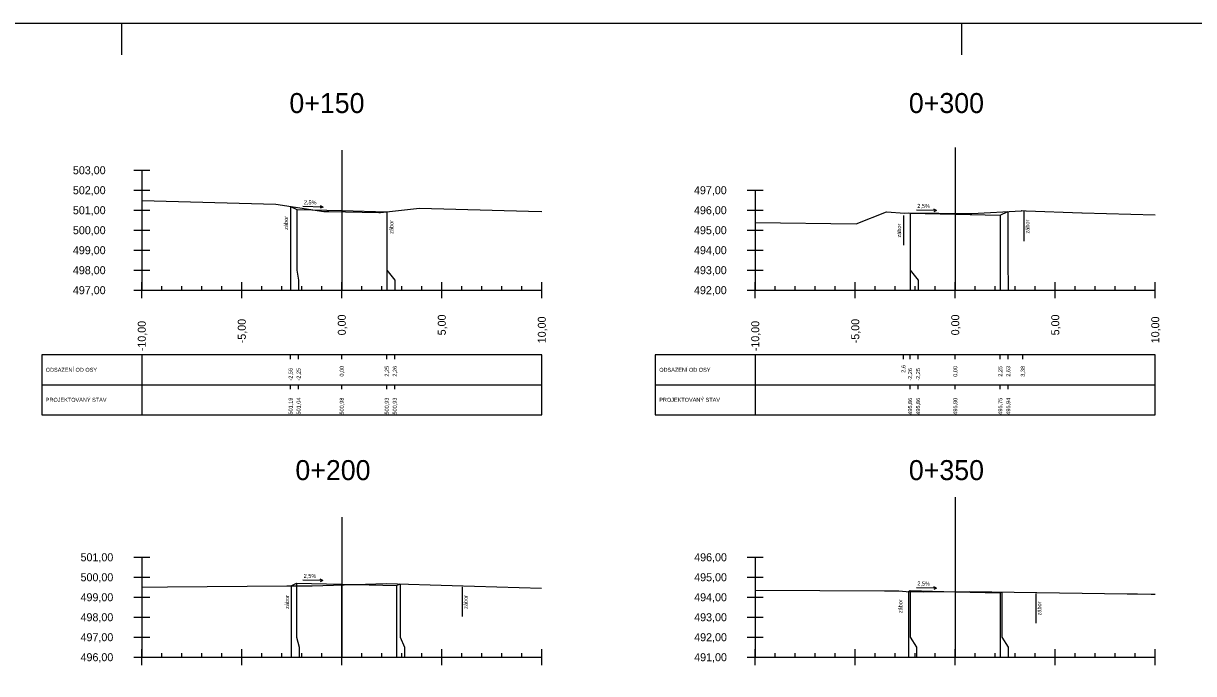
# Model space of a CAD drawing. Extents: x -631407 to -631215, y -1089700 to -1088598.
# Drawn here: x -631373.8 to -631315.3, y -1088714 to -1088681.5 of the extents above; entities that cross this region are included whole.
import ezdxf

# ---------------------------------------------------------------- set-up
doc = ezdxf.new("R2010")
doc.units = 0
for name, color, linetype in [('08_LEGENDA_HV', 7, 'Continuous'), ('59', 7, 'Continuous'), ('DTM-Breaklines', 7, 'Continuous'), ('NIVELETA_VYSKY', 7, 'Continuous'), ('REZ_BODY', 7, 'Continuous'), ('REZ_ODSTUPY', 7, 'Continuous'), ('REZ_POPIS', 7, 'Continuous'), ('REZ_RAMY', 7, 'Continuous'), ('REZ_STANICENI', 7, 'Continuous'), ('REZ_SVISLE', 7, 'Continuous'), ('REZ_TENKA', 7, 'Continuous'), ('REZ_TLUSTA', 7, 'Continuous'), ('TABULKA_POPIS', 7, 'Continuous'), ('TEREN', 7, 'Continuous'), ('zábor', 7, 'Continuous')]:
    doc.layers.add(name, color=color, linetype=linetype)

msp = doc.modelspace()

# ---------------------------------------------------------------- linework, layer by layer
at = {"layer": '08_LEGENDA_HV'}
msp.add_lwpolyline([(-631242.839, -1088740.87), (-631242.839, -1088681.47), (-631407.014, -1088681.47), (-631407.014, -1088740.87)], close=True, dxfattribs=at)
at = {"layer": '59'}
for p, q in [((-631368.243, -1088688.817), (-631367.443, -1088688.817)), ((-631367.843, -1088688.817), (-631367.843, -1088694.817)), ((-631368.243, -1088689.817), (-631367.443, -1088689.817)), ((-631337.571, -1088689.817), (-631336.771, -1088689.817)), ((-631337.171, -1088689.817), (-631337.171, -1088694.817)), ((-631368.243, -1088690.817), (-631367.443, -1088690.817)), ((-631337.571, -1088690.817), (-631336.771, -1088690.817)), ((-631368.243, -1088691.817), (-631367.443, -1088691.817)), ((-631337.571, -1088691.817), (-631336.771, -1088691.817)), ((-631368.243, -1088692.817), (-631367.443, -1088692.817)), ((-631337.571, -1088692.817), (-631336.771, -1088692.817)), ((-631368.243, -1088693.817), (-631367.443, -1088693.817)), ((-631337.571, -1088693.817), (-631336.771, -1088693.817)), ((-631368.243, -1088694.817), (-631367.443, -1088694.817)), ((-631337.571, -1088694.817), (-631336.771, -1088694.817)), ((-631368.243, -1088708.178), (-631367.443, -1088708.178)), ((-631367.843, -1088708.178), (-631367.843, -1088713.178)), ((-631337.571, -1088708.178), (-631336.771, -1088708.178)), ((-631337.171, -1088708.178), (-631337.171, -1088713.178)), ((-631368.243, -1088709.178), (-631367.443, -1088709.178)), ((-631337.571, -1088709.178), (-631336.771, -1088709.178)), ((-631368.243, -1088710.178), (-631367.443, -1088710.178)), ((-631337.571, -1088710.178), (-631336.771, -1088710.178)), ((-631368.243, -1088711.178), (-631367.443, -1088711.178)), ((-631337.571, -1088711.178), (-631336.771, -1088711.178)), ((-631368.243, -1088712.178), (-631367.443, -1088712.178)), ((-631337.571, -1088712.178), (-631336.771, -1088712.178)), ((-631368.243, -1088713.178), (-631367.443, -1088713.178)), ((-631337.571, -1088713.178), (-631336.771, -1088713.178))]:
    msp.add_line(p, q, dxfattribs=at)
at = {"layer": 'DTM-Breaklines'}
for p, q in [((-631368.839, -1088683.051), (-631368.839, -1088681.47)), ((-631326.839, -1088683.051), (-631326.839, -1088681.47))]:
    msp.add_line(p, q, dxfattribs=at)
at = {"layer": 'REZ_RAMY'}
for p, q in [((-631372.843, -1088698.05), (-631372.843, -1088701.05)), ((-631367.843, -1088698.05), (-631367.843, -1088701.05)), ((-631360.403, -1088698.26), (-631360.403, -1088698.06)), ((-631360.003, -1088698.26), (-631360.003, -1088698.06)), ((-631357.843, -1088698.26), (-631357.843, -1088698.06)), ((-631355.593, -1088698.26), (-631355.593, -1088698.06)), ((-631355.193, -1088698.26), (-631355.193, -1088698.06)), ((-631342.171, -1088698.05), (-631342.171, -1088701.05)), ((-631337.171, -1088698.05), (-631337.171, -1088701.05)), ((-631329.764, -1088698.269), (-631329.764, -1088698.069)), ((-631329.428, -1088698.269), (-631329.428, -1088698.069)), ((-631329.028, -1088698.269), (-631329.028, -1088698.069)), ((-631327.171, -1088698.269), (-631327.171, -1088698.069)), ((-631324.921, -1088698.269), (-631324.921, -1088698.069)), ((-631324.521, -1088698.269), (-631324.521, -1088698.069)), ((-631323.795, -1088698.269), (-631323.795, -1088698.069)), ((-631372.843, -1088699.55), (-631347.843, -1088699.55)), ((-631360.403, -1088699.76), (-631360.403, -1088699.56)), ((-631360.003, -1088699.76), (-631360.003, -1088699.56)), ((-631357.843, -1088699.76), (-631357.843, -1088699.56)), ((-631355.593, -1088699.76), (-631355.593, -1088699.56)), ((-631355.193, -1088699.76), (-631355.193, -1088699.56)), ((-631342.171, -1088699.55), (-631317.171, -1088699.55)), ((-631329.428, -1088699.769), (-631329.428, -1088699.569)), ((-631329.028, -1088699.769), (-631329.028, -1088699.569)), ((-631327.171, -1088699.769), (-631327.171, -1088699.569)), ((-631324.921, -1088699.769), (-631324.921, -1088699.569)), ((-631324.521, -1088699.769), (-631324.521, -1088699.569))]:
    msp.add_line(p, q, dxfattribs=at)
for points in [[(-631372.843, -1088698.05), (-631372.843, -1088701.05), (-631347.843, -1088701.05), (-631347.843, -1088698.05)], [(-631342.171, -1088698.05), (-631342.171, -1088701.05), (-631317.171, -1088701.05), (-631317.171, -1088698.05)]]:
    msp.add_lwpolyline(points, close=True, dxfattribs=at)
at = {"layer": 'REZ_SVISLE'}
for points in [[(-631360.403, -1088690.624), (-631360.403, -1088693.817), (-631360.403, -1088694.317), (-631360.403, -1088694.817)], [(-631360.093, -1088690.779), (-631360.093, -1088693.817), (-631360.003, -1088694.317), (-631360.003, -1088694.817)], [(-631357.843, -1088690.835), (-631357.843, -1088693.817), (-631357.843, -1088694.317), (-631357.843, -1088694.817)], [(-631355.593, -1088690.891), (-631355.593, -1088693.817), (-631355.593, -1088694.317), (-631355.593, -1088694.817)], [(-631355.588, -1088690.889), (-631355.588, -1088693.817), (-631355.193, -1088694.317), (-631355.193, -1088694.817)], [(-631329.428, -1088690.954), (-631329.428, -1088693.817), (-631329.428, -1088694.317), (-631329.428, -1088694.817)], [(-631329.421, -1088690.957), (-631329.421, -1088693.817), (-631329.028, -1088694.317), (-631329.028, -1088694.817)], [(-631327.171, -1088691.014), (-631327.171, -1088693.817), (-631327.171, -1088694.317), (-631327.171, -1088694.817)], [(-631324.921, -1088691.07), (-631324.921, -1088693.817), (-631324.921, -1088694.317), (-631324.921, -1088694.817)], [(-631324.541, -1088690.88), (-631324.541, -1088693.817), (-631324.521, -1088694.317), (-631324.521, -1088694.817)], [(-631360.37, -1088709.602), (-631360.37, -1088712.178), (-631360.37, -1088712.678), (-631360.37, -1088713.178)], [(-631360.101, -1088709.467), (-631360.101, -1088712.178), (-631359.97, -1088712.678), (-631359.97, -1088713.178)], [(-631357.851, -1088709.523), (-631357.851, -1088712.178), (-631357.851, -1088712.678), (-631357.851, -1088713.178)], [(-631355.101, -1088709.592), (-631355.101, -1088712.178), (-631355.101, -1088712.678), (-631355.101, -1088713.178)], [(-631354.93, -1088709.507), (-631354.93, -1088712.178), (-631354.701, -1088712.678), (-631354.701, -1088713.178)], [(-631329.512, -1088709.893), (-631329.512, -1088712.178), (-631329.512, -1088712.678), (-631329.512, -1088713.178)], [(-631329.421, -1088709.848), (-631329.421, -1088712.178), (-631329.112, -1088712.678), (-631329.112, -1088713.178)], [(-631327.171, -1088709.904), (-631327.171, -1088712.178), (-631327.171, -1088712.678), (-631327.171, -1088713.178)], [(-631324.921, -1088709.96), (-631324.921, -1088712.178), (-631324.921, -1088712.678), (-631324.921, -1088713.178)], [(-631324.835, -1088709.917), (-631324.835, -1088712.178), (-631324.521, -1088712.678), (-631324.521, -1088713.178)]]:
    msp.add_lwpolyline(points, dxfattribs=at)
at = {"layer": 'REZ_TENKA'}
for p, q in [((-631366.843, -1088694.817), (-631366.843, -1088694.617)), ((-631365.843, -1088694.817), (-631365.843, -1088694.617)), ((-631364.843, -1088694.817), (-631364.843, -1088694.617)), ((-631363.843, -1088694.817), (-631363.843, -1088694.617)), ((-631361.843, -1088694.817), (-631361.843, -1088694.617)), ((-631360.843, -1088694.817), (-631360.843, -1088694.617)), ((-631359.843, -1088694.817), (-631359.843, -1088694.617)), ((-631358.843, -1088694.817), (-631358.843, -1088694.617)), ((-631356.843, -1088694.817), (-631356.843, -1088694.617)), ((-631355.843, -1088694.817), (-631355.843, -1088694.617)), ((-631354.843, -1088694.817), (-631354.843, -1088694.617)), ((-631353.843, -1088694.817), (-631353.843, -1088694.617)), ((-631351.843, -1088694.817), (-631351.843, -1088694.617)), ((-631350.843, -1088694.817), (-631350.843, -1088694.617)), ((-631349.843, -1088694.817), (-631349.843, -1088694.617)), ((-631348.843, -1088694.817), (-631348.843, -1088694.617)), ((-631336.171, -1088694.817), (-631336.171, -1088694.617)), ((-631335.171, -1088694.817), (-631335.171, -1088694.617)), ((-631334.171, -1088694.817), (-631334.171, -1088694.617)), ((-631333.171, -1088694.817), (-631333.171, -1088694.617)), ((-631331.171, -1088694.817), (-631331.171, -1088694.617)), ((-631330.171, -1088694.817), (-631330.171, -1088694.617)), ((-631329.171, -1088694.817), (-631329.171, -1088694.617)), ((-631328.171, -1088694.817), (-631328.171, -1088694.617)), ((-631326.171, -1088694.817), (-631326.171, -1088694.617)), ((-631325.171, -1088694.817), (-631325.171, -1088694.617)), ((-631324.171, -1088694.817), (-631324.171, -1088694.617)), ((-631323.171, -1088694.817), (-631323.171, -1088694.617)), ((-631321.171, -1088694.817), (-631321.171, -1088694.617)), ((-631320.171, -1088694.817), (-631320.171, -1088694.617)), ((-631319.171, -1088694.817), (-631319.171, -1088694.617)), ((-631318.171, -1088694.817), (-631318.171, -1088694.617)), ((-631366.843, -1088713.178), (-631366.843, -1088712.978)), ((-631365.843, -1088713.178), (-631365.843, -1088712.978)), ((-631364.843, -1088713.178), (-631364.843, -1088712.978)), ((-631363.843, -1088713.178), (-631363.843, -1088712.978)), ((-631361.843, -1088713.178), (-631361.843, -1088712.978)), ((-631360.843, -1088713.178), (-631360.843, -1088712.978)), ((-631359.843, -1088713.178), (-631359.843, -1088712.978)), ((-631358.843, -1088713.178), (-631358.843, -1088712.978)), ((-631356.843, -1088713.178), (-631356.843, -1088712.978)), ((-631355.843, -1088713.178), (-631355.843, -1088712.978)), ((-631354.843, -1088713.178), (-631354.843, -1088712.978)), ((-631353.843, -1088713.178), (-631353.843, -1088712.978)), ((-631351.843, -1088713.178), (-631351.843, -1088712.978)), ((-631350.843, -1088713.178), (-631350.843, -1088712.978)), ((-631349.843, -1088713.178), (-631349.843, -1088712.978)), ((-631348.843, -1088713.178), (-631348.843, -1088712.978)), ((-631336.171, -1088713.178), (-631336.171, -1088712.978)), ((-631335.171, -1088713.178), (-631335.171, -1088712.978)), ((-631334.171, -1088713.178), (-631334.171, -1088712.978)), ((-631333.171, -1088713.178), (-631333.171, -1088712.978)), ((-631331.171, -1088713.178), (-631331.171, -1088712.978)), ((-631330.171, -1088713.178), (-631330.171, -1088712.978)), ((-631329.171, -1088713.178), (-631329.171, -1088712.978)), ((-631328.171, -1088713.178), (-631328.171, -1088712.978)), ((-631326.171, -1088713.178), (-631326.171, -1088712.978)), ((-631325.171, -1088713.178), (-631325.171, -1088712.978)), ((-631324.171, -1088713.178), (-631324.171, -1088712.978)), ((-631323.171, -1088713.178), (-631323.171, -1088712.978)), ((-631321.171, -1088713.178), (-631321.171, -1088712.978)), ((-631320.171, -1088713.178), (-631320.171, -1088712.978)), ((-631319.171, -1088713.178), (-631319.171, -1088712.978)), ((-631318.171, -1088713.178), (-631318.171, -1088712.978))]:
    msp.add_line(p, q, dxfattribs=at)
at = {"layer": 'REZ_TLUSTA'}
for p, q in [((-631357.843, -1088687.817), (-631357.843, -1088694.817)), ((-631327.171, -1088687.686), (-631327.171, -1088694.817)), ((-631367.843, -1088695.217), (-631367.843, -1088694.417)), ((-631362.843, -1088695.217), (-631362.843, -1088694.417)), ((-631357.843, -1088695.217), (-631357.843, -1088694.417)), ((-631352.843, -1088695.217), (-631352.843, -1088694.417)), ((-631347.843, -1088695.217), (-631347.843, -1088694.417)), ((-631337.171, -1088695.217), (-631337.171, -1088694.417)), ((-631332.171, -1088695.217), (-631332.171, -1088694.417)), ((-631327.171, -1088695.217), (-631327.171, -1088694.417)), ((-631322.171, -1088695.217), (-631322.171, -1088694.417)), ((-631317.171, -1088695.217), (-631317.171, -1088694.417)), ((-631367.843, -1088694.817), (-631347.843, -1088694.817)), ((-631337.171, -1088694.817), (-631317.171, -1088694.817)), ((-631327.171, -1088705.178), (-631327.171, -1088713.178)), ((-631357.843, -1088706.178), (-631357.843, -1088713.178)), ((-631367.843, -1088713.578), (-631367.843, -1088712.778)), ((-631362.843, -1088713.578), (-631362.843, -1088712.778)), ((-631357.843, -1088713.578), (-631357.843, -1088712.778)), ((-631352.843, -1088713.578), (-631352.843, -1088712.778)), ((-631347.843, -1088713.578), (-631347.843, -1088712.778)), ((-631337.171, -1088713.578), (-631337.171, -1088712.778)), ((-631332.171, -1088713.578), (-631332.171, -1088712.778)), ((-631327.171, -1088713.578), (-631327.171, -1088712.778)), ((-631322.171, -1088713.578), (-631322.171, -1088712.778)), ((-631317.171, -1088713.578), (-631317.171, -1088712.778)), ((-631367.843, -1088713.178), (-631347.843, -1088713.178)), ((-631337.171, -1088713.178), (-631317.171, -1088713.178))]:
    msp.add_line(p, q, dxfattribs=at)
at = {"layer": 'TEREN'}
for points in [[(-631367.843, -1088690.323), (-631361.133, -1088690.514), (-631358.738, -1088690.874), (-631358.715, -1088690.88), (-631358.485, -1088690.883), (-631355.988, -1088690.932), (-631355.911, -1088690.923), (-631353.954, -1088690.718), (-631348.507, -1088690.866), (-631347.843, -1088690.873)], [(-631360.403, -1088690.624), (-631360.093, -1088690.779), (-631357.843, -1088690.835), (-631355.593, -1088690.891), (-631355.588, -1088690.889)], [(-631337.181, -1088691.424), (-631332.117, -1088691.505), (-631330.608, -1088690.901), (-631329.689, -1088690.963), (-631329.484, -1088690.953), (-631326.468, -1088690.983), (-631326.347, -1088690.985), (-631323.862, -1088690.84), (-631323.836, -1088690.838), (-631323.637, -1088690.845), (-631323.636, -1088690.845), (-631323.626, -1088690.845), (-631320.835, -1088690.945), (-631320.82, -1088690.945), (-631317.181, -1088691.041)], [(-631329.428, -1088690.954), (-631329.421, -1088690.957), (-631327.171, -1088691.014), (-631324.921, -1088691.07), (-631324.541, -1088690.88)], [(-631367.851, -1088709.665), (-631366.555, -1088709.653), (-631360.584, -1088709.601), (-631359.318, -1088709.603), (-631357.731, -1088709.561), (-631355.61, -1088709.486), (-631352.331, -1088709.588), (-631347.851, -1088709.72)], [(-631360.37, -1088709.602), (-631360.101, -1088709.467), (-631357.851, -1088709.523), (-631355.101, -1088709.592), (-631354.93, -1088709.507)], [(-631337.171, -1088709.821), (-631330.712, -1088709.861), (-631329.995, -1088709.859), (-631329.622, -1088709.892), (-631328.783, -1088709.899), (-631326.482, -1088709.894), (-631318.582, -1088710.005), (-631318.25, -1088710.004), (-631318.052, -1088710.006), (-631317.384, -1088710.02), (-631317.171, -1088710.025)], [(-631329.512, -1088709.893), (-631329.421, -1088709.848), (-631327.171, -1088709.904), (-631324.921, -1088709.96), (-631324.835, -1088709.917)]]:
    msp.add_lwpolyline(points, dxfattribs=at)
at = {"layer": 'zábor'}
for p, q in [((-631358.776, -1088690.656), (-631359.784, -1088690.63)), ((-631358.776, -1088690.656), (-631358.916, -1088690.713)), ((-631358.776, -1088690.656), (-631358.913, -1088690.591)), ((-631329.752, -1088691.084), (-631329.752, -1088692.565)), ((-631328.104, -1088690.834), (-631329.112, -1088690.809)), ((-631328.104, -1088690.834), (-631328.243, -1088690.892)), ((-631328.104, -1088690.834), (-631328.24, -1088690.769)), ((-631323.74, -1088690.885), (-631323.74, -1088692.366)), ((-631358.784, -1088709.344), (-631358.921, -1088709.279)), ((-631358.784, -1088709.344), (-631359.792, -1088709.319)), ((-631358.784, -1088709.344), (-631358.924, -1088709.401)), ((-631351.827, -1088709.661), (-631351.827, -1088711.142)), ((-631328.104, -1088709.724), (-631329.112, -1088709.699)), ((-631328.104, -1088709.724), (-631328.243, -1088709.782)), ((-631328.104, -1088709.724), (-631328.24, -1088709.66)), ((-631323.148, -1088709.986), (-631323.148, -1088711.467))]:
    msp.add_line(p, q, dxfattribs=at)

# ---------------------------------------------------------------- texts
at = {"layer": 'NIVELETA_VYSKY'}
for s, p in [('501,19', (-631360.303, -1088701.036)), ('501,04', (-631359.903, -1088701.036)), ('500,98', (-631357.743, -1088701.036)), ('500,93', (-631355.493, -1088701.036)), ('500,93', (-631355.093, -1088701.036)), ('495,86', (-631329.328, -1088701.045)), ('495,86', (-631328.928, -1088701.045)), ('495,80', (-631327.071, -1088701.045)), ('495,75', (-631324.821, -1088701.045)), ('495,94', (-631324.421, -1088701.045))]:
    msp.add_text(s, height=0.2, rotation=90, dxfattribs=at).set_placement(p)
at = {"layer": 'REZ_BODY'}
for s, p in [('-2,56', (-631360.303, -1088699.338)), ('-2,25', (-631359.903, -1088699.338)), ('0,00', (-631357.743, -1088699.139)), ('2,25', (-631355.493, -1088699.139)), ('2,26', (-631355.093, -1088699.139)), ('2,6', (-631329.664, -1088698.948)), ('-2,26', (-631329.328, -1088699.346)), ('-2,25', (-631328.928, -1088699.346)), ('0,00', (-631327.071, -1088699.148)), ('2,25', (-631324.821, -1088699.148)), ('2,63', (-631324.421, -1088699.148)), ('3,38', (-631323.695, -1088699.148))]:
    msp.add_text(s, height=0.2, rotation=90, dxfattribs=at).set_placement(p)
at = {"layer": 'REZ_ODSTUPY'}
for s, p in [('-10,00', (-631367.643, -1088697.869)), ('-5,00', (-631362.643, -1088697.472)), ('0,00', (-631357.643, -1088697.075)), ('5,00', (-631352.643, -1088697.075)), ('10,00', (-631347.643, -1088697.472)), ('-10,00', (-631336.971, -1088697.869)), ('-5,00', (-631331.971, -1088697.472)), ('0,00', (-631326.971, -1088697.075)), ('5,00', (-631321.971, -1088697.075)), ('10,00', (-631316.971, -1088697.472))]:
    msp.add_text(s, height=0.4, rotation=90, dxfattribs=at).set_placement(p)
at = {"layer": 'REZ_POPIS'}
for s, p in [('503,00', (-631371.286, -1088689.017)), ('502,00', (-631371.286, -1088690.017)), ('497,00', (-631340.233, -1088690.017)), ('501,00', (-631371.286, -1088691.017)), ('496,00', (-631340.233, -1088691.017)), ('500,00', (-631371.286, -1088692.017)), ('495,00', (-631340.233, -1088692.017)), ('499,00', (-631371.286, -1088693.017)), ('494,00', (-631340.233, -1088693.017)), ('498,00', (-631371.286, -1088694.017)), ('493,00', (-631340.233, -1088694.017)), ('497,00', (-631371.286, -1088695.017)), ('492,00', (-631340.233, -1088695.017)), ('501,00', (-631370.903, -1088708.378)), ('496,00', (-631340.223, -1088708.378)), ('500,00', (-631370.903, -1088709.378)), ('495,00', (-631340.223, -1088709.378)), ('499,00', (-631370.903, -1088710.378)), ('494,00', (-631340.223, -1088710.378)), ('498,00', (-631370.903, -1088711.378)), ('493,00', (-631340.223, -1088711.378)), ('497,00', (-631370.903, -1088712.378)), ('492,00', (-631340.223, -1088712.378)), ('496,00', (-631370.903, -1088713.378)), ('491,00', (-631340.223, -1088713.378))]:
    msp.add_text(s, height=0.4, dxfattribs=at).set_placement(p)
at = {"layer": 'REZ_STANICENI'}
for s, p in [('0+150', (-631360.462, -1088685.955)), ('0+300', (-631329.49, -1088685.955)), ('0+200', (-631360.162, -1088704.317)), ('0+350', (-631329.49, -1088704.317))]:
    msp.add_text(s, height=1, dxfattribs=at).set_placement(p)
at = {"layer": 'TABULKA_POPIS'}
for s, p in [('ODSAZENÍ OD OSY', (-631372.643, -1088698.9)), ('ODSAZENÍ OD OSY', (-631341.971, -1088698.9)), ('PROJEKTOVANÝ STAV', (-631372.643, -1088700.4)), ('PROJEKTOVANÝ STAV', (-631341.971, -1088700.4))]:
    msp.add_text(s, height=0.2, dxfattribs=at).set_placement(p)
at = {"layer": 'zábor'}
for s, rotation, p in [('2,5%', 358.5679, (-631359.74, -1088690.519)), ('2,5%', 358.5679, (-631329.068, -1088690.697)), ('zábor', 90, (-631360.535, -1088691.794)), ('zábor', 90, (-631355.262, -1088691.997)), ('zábor', 90, (-631329.877, -1088692.182)), ('zábor', 90, (-631323.462, -1088691.982)), ('2,5%', 358.5679, (-631359.748, -1088709.207)), ('2,5%', 358.5679, (-631329.068, -1088709.587)), ('zábor', 90, (-631360.484, -1088710.759)), ('zábor', 90, (-631351.55, -1088710.759)), ('zábor', 90, (-631329.812, -1088710.973)), ('zábor', 90, (-631322.871, -1088711.084))]:
    msp.add_text(s, height=0.2, rotation=rotation, dxfattribs=at).set_placement(p)

doc.saveas('drawing.dxf')
